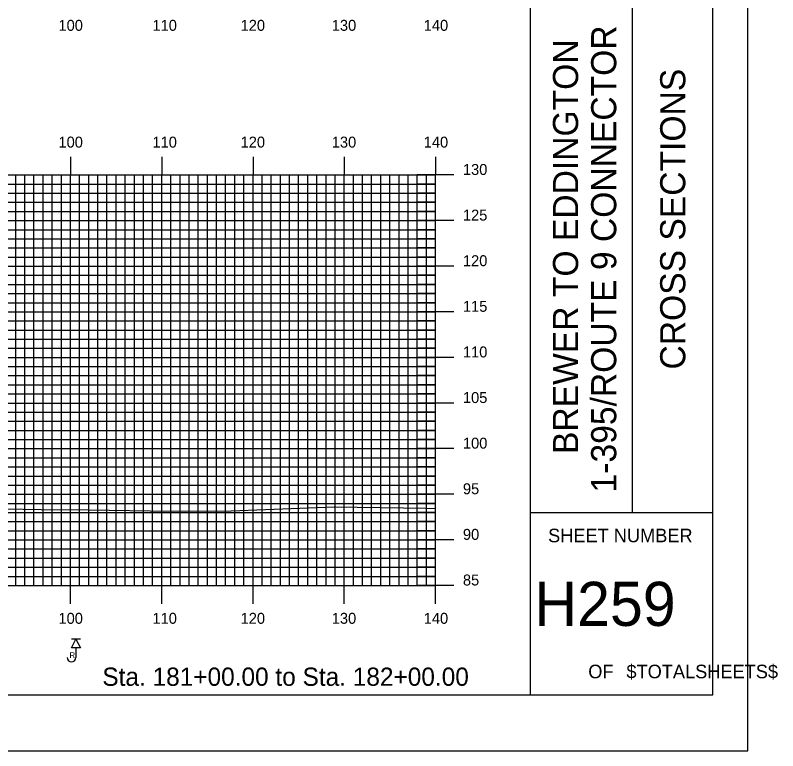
# Model space of a CAD drawing. Extents: x 1786189 to 1786532, y 442591 to 442811.
# Drawn here: x 1786448.5 to 1786532.1, y 442590.5 to 442671.2 of the extents above; entities that cross this region are included whole.
import ezdxf

# ---------------------------------------------------------------- set-up
doc = ezdxf.new("R2010")
doc.units = 0
for name, color, linetype in [('BORDER', 7, 'Continuous'), ('BORING - REFUSAL', 7, 'Continuous'), ('H_V ANNOTATION', 7, 'Continuous'), ('MAJOR', 7, 'Continuous'), ('MINOR', 7, 'Continuous'), ('PLOT BOUNDARY', 7, 'Continuous'), ('S_Roadway_Centerline', 7, 'Continuous')]:
    doc.layers.add(name, color=color, linetype=linetype)

msp = doc.modelspace()

# ---------------------------------------------------------------- linework, layer by layer
at = {"layer": 'BORDER'}
for p, q in [((1786504.965, 442596.665), (1786504.965, 442806.665)), ((1786516.147, 442616.671), (1786516.147, 442686.671)), ((1786504.965, 442616.671), (1786524.965, 442616.671))]:
    msp.add_line(p, q, dxfattribs=at)
msp.add_lwpolyline([(1786204.965, 442596.665), (1786524.965, 442596.665), (1786524.965, 442806.665), (1786204.965, 442806.665)], close=True, dxfattribs=at)
at = {"layer": 'BORING - REFUSAL'}
for p, q in [((1786455.645, 442602.782), (1786454.685, 442602.782)), ((1786455.165, 442601.822), (1786455.165, 442600.763))]:
    msp.add_line(p, q, dxfattribs=at)
msp.add_lwpolyline([(1786455.165, 442602.782), (1786455.645, 442601.822), (1786454.685, 442601.822)], close=True, dxfattribs=at)
msp.add_arc((1786454.68, 442600.763), 0.485, 180, 0, dxfattribs=at)
at = {"layer": 'MAJOR'}
for p, q in [((1786454.565, 442655.669), (1786454.565, 442653.665)), ((1786464.565, 442655.669), (1786464.565, 442653.665)), ((1786474.565, 442655.669), (1786474.565, 442653.665)), ((1786484.565, 442655.669), (1786484.565, 442653.665)), ((1786494.565, 442655.669), (1786494.565, 442653.665)), ((1786214.565, 442653.665), (1786494.565, 442653.665)), ((1786214.565, 442653.665), (1786494.565, 442653.665)), ((1786454.565, 442608.665), (1786454.565, 442653.665)), ((1786464.565, 442608.665), (1786464.565, 442653.665)), ((1786474.565, 442608.665), (1786474.565, 442653.665)), ((1786484.565, 442608.665), (1786484.565, 442653.665)), ((1786496.569, 442653.665), (1786492.561, 442653.665)), ((1786494.565, 442608.665), (1786494.565, 442653.665)), ((1786494.565, 442608.665), (1786494.565, 442653.665)), ((1786214.565, 442648.665), (1786494.565, 442648.665)), ((1786496.569, 442648.665), (1786492.561, 442648.665)), ((1786214.565, 442643.665), (1786494.565, 442643.665)), ((1786496.569, 442643.665), (1786492.561, 442643.665)), ((1786214.565, 442638.665), (1786494.565, 442638.665)), ((1786496.569, 442638.665), (1786492.561, 442638.665)), ((1786214.565, 442633.665), (1786494.565, 442633.665)), ((1786496.569, 442633.665), (1786492.561, 442633.665)), ((1786214.565, 442628.665), (1786494.565, 442628.665)), ((1786496.569, 442628.665), (1786492.561, 442628.665)), ((1786214.565, 442623.665), (1786494.565, 442623.665)), ((1786496.569, 442623.665), (1786492.561, 442623.665)), ((1786214.565, 442618.665), (1786494.565, 442618.665)), ((1786496.569, 442618.665), (1786492.561, 442618.665)), ((1786214.565, 442613.665), (1786494.565, 442613.665)), ((1786496.569, 442613.665), (1786492.561, 442613.665)), ((1786214.565, 442608.665), (1786494.565, 442608.665)), ((1786214.565, 442608.665), (1786494.565, 442608.665)), ((1786454.565, 442606.661), (1786454.565, 442608.665)), ((1786464.565, 442606.661), (1786464.565, 442608.665)), ((1786474.565, 442606.661), (1786474.565, 442608.665)), ((1786484.565, 442606.661), (1786484.565, 442608.665)), ((1786496.569, 442608.665), (1786492.561, 442608.665)), ((1786494.565, 442606.661), (1786494.565, 442608.665))]:
    msp.add_line(p, q, dxfattribs=at)
at = {"layer": 'MINOR'}
for p, q in [((1786448.565, 442608.665), (1786448.565, 442653.665)), ((1786449.565, 442608.665), (1786449.565, 442653.665)), ((1786450.565, 442608.665), (1786450.565, 442653.665)), ((1786451.565, 442608.665), (1786451.565, 442653.665)), ((1786452.565, 442608.665), (1786452.565, 442653.665)), ((1786453.565, 442608.665), (1786453.565, 442653.665)), ((1786455.565, 442608.665), (1786455.565, 442653.665)), ((1786456.565, 442608.665), (1786456.565, 442653.665)), ((1786457.565, 442608.665), (1786457.565, 442653.665)), ((1786458.565, 442608.665), (1786458.565, 442653.665)), ((1786459.565, 442608.665), (1786459.565, 442653.665)), ((1786460.565, 442608.665), (1786460.565, 442653.665)), ((1786461.565, 442608.665), (1786461.565, 442653.665)), ((1786462.565, 442608.665), (1786462.565, 442653.665)), ((1786463.565, 442608.665), (1786463.565, 442653.665)), ((1786465.565, 442608.665), (1786465.565, 442653.665)), ((1786466.565, 442608.665), (1786466.565, 442653.665)), ((1786467.565, 442608.665), (1786467.565, 442653.665)), ((1786468.565, 442608.665), (1786468.565, 442653.665)), ((1786469.565, 442608.665), (1786469.565, 442653.665)), ((1786470.565, 442608.665), (1786470.565, 442653.665)), ((1786471.565, 442608.665), (1786471.565, 442653.665)), ((1786472.565, 442608.665), (1786472.565, 442653.665)), ((1786473.565, 442608.665), (1786473.565, 442653.665)), ((1786475.565, 442608.665), (1786475.565, 442653.665)), ((1786476.565, 442608.665), (1786476.565, 442653.665)), ((1786477.565, 442608.665), (1786477.565, 442653.665)), ((1786478.565, 442608.665), (1786478.565, 442653.665)), ((1786479.565, 442608.665), (1786479.565, 442653.665)), ((1786480.565, 442608.665), (1786480.565, 442653.665)), ((1786481.565, 442608.665), (1786481.565, 442653.665)), ((1786482.565, 442608.665), (1786482.565, 442653.665)), ((1786483.565, 442608.665), (1786483.565, 442653.665)), ((1786485.565, 442608.665), (1786485.565, 442653.665)), ((1786486.565, 442608.665), (1786486.565, 442653.665)), ((1786487.565, 442608.665), (1786487.565, 442653.665)), ((1786488.565, 442608.665), (1786488.565, 442653.665)), ((1786489.565, 442608.665), (1786489.565, 442653.665)), ((1786490.565, 442608.665), (1786490.565, 442653.665)), ((1786491.565, 442608.665), (1786491.565, 442653.665)), ((1786492.565, 442608.665), (1786492.565, 442653.665)), ((1786493.565, 442608.665), (1786493.565, 442653.665)), ((1786214.565, 442652.665), (1786494.565, 442652.665)), ((1786494.565, 442652.665), (1786492.561, 442652.665)), ((1786214.565, 442651.665), (1786494.565, 442651.665)), ((1786494.565, 442651.665), (1786492.561, 442651.665)), ((1786214.565, 442650.665), (1786494.565, 442650.665)), ((1786494.565, 442650.665), (1786492.561, 442650.665)), ((1786214.565, 442649.665), (1786494.565, 442649.665)), ((1786494.565, 442649.665), (1786492.561, 442649.665)), ((1786214.565, 442647.665), (1786494.565, 442647.665)), ((1786494.565, 442647.665), (1786492.561, 442647.665)), ((1786214.565, 442646.665), (1786494.565, 442646.665)), ((1786494.565, 442646.665), (1786492.561, 442646.665)), ((1786214.565, 442645.665), (1786494.565, 442645.665)), ((1786494.565, 442645.665), (1786492.561, 442645.665)), ((1786214.565, 442644.665), (1786494.565, 442644.665)), ((1786494.565, 442644.665), (1786492.561, 442644.665)), ((1786214.565, 442642.665), (1786494.565, 442642.665)), ((1786494.565, 442642.665), (1786492.561, 442642.665)), ((1786214.565, 442641.665), (1786494.565, 442641.665)), ((1786494.565, 442641.665), (1786492.561, 442641.665)), ((1786214.565, 442640.665), (1786494.565, 442640.665)), ((1786494.565, 442640.665), (1786492.561, 442640.665)), ((1786214.565, 442639.665), (1786494.565, 442639.665)), ((1786494.565, 442639.665), (1786492.561, 442639.665)), ((1786214.565, 442637.665), (1786494.565, 442637.665)), ((1786494.565, 442637.665), (1786492.561, 442637.665)), ((1786214.565, 442636.665), (1786494.565, 442636.665)), ((1786494.565, 442636.665), (1786492.561, 442636.665)), ((1786214.565, 442635.665), (1786494.565, 442635.665)), ((1786494.565, 442635.665), (1786492.561, 442635.665)), ((1786214.565, 442634.665), (1786494.565, 442634.665)), ((1786494.565, 442634.665), (1786492.561, 442634.665)), ((1786214.565, 442632.665), (1786494.565, 442632.665)), ((1786494.565, 442632.665), (1786492.561, 442632.665)), ((1786214.565, 442631.665), (1786494.565, 442631.665)), ((1786494.565, 442631.665), (1786492.561, 442631.665)), ((1786214.565, 442630.665), (1786494.565, 442630.665)), ((1786494.565, 442630.665), (1786492.561, 442630.665)), ((1786214.565, 442629.665), (1786494.565, 442629.665)), ((1786494.565, 442629.665), (1786492.561, 442629.665)), ((1786214.565, 442627.665), (1786494.565, 442627.665)), ((1786494.565, 442627.665), (1786492.561, 442627.665)), ((1786214.565, 442626.665), (1786494.565, 442626.665)), ((1786494.565, 442626.665), (1786492.561, 442626.665)), ((1786214.565, 442625.665), (1786494.565, 442625.665)), ((1786494.565, 442625.665), (1786492.561, 442625.665)), ((1786214.565, 442624.665), (1786494.565, 442624.665)), ((1786494.565, 442624.665), (1786492.561, 442624.665)), ((1786214.565, 442622.665), (1786494.565, 442622.665)), ((1786494.565, 442622.665), (1786492.561, 442622.665)), ((1786214.565, 442621.665), (1786494.565, 442621.665)), ((1786494.565, 442621.665), (1786492.561, 442621.665)), ((1786214.565, 442620.665), (1786494.565, 442620.665)), ((1786494.565, 442620.665), (1786492.561, 442620.665)), ((1786214.565, 442619.665), (1786494.565, 442619.665)), ((1786494.565, 442619.665), (1786492.561, 442619.665)), ((1786214.565, 442617.665), (1786494.565, 442617.665)), ((1786494.565, 442617.665), (1786492.561, 442617.665)), ((1786214.565, 442616.665), (1786494.565, 442616.665)), ((1786494.565, 442616.665), (1786492.561, 442616.665)), ((1786214.565, 442615.665), (1786494.565, 442615.665)), ((1786494.565, 442615.665), (1786492.561, 442615.665)), ((1786214.565, 442614.665), (1786494.565, 442614.665)), ((1786494.565, 442614.665), (1786492.561, 442614.665)), ((1786214.565, 442612.665), (1786494.565, 442612.665)), ((1786494.565, 442612.665), (1786492.561, 442612.665)), ((1786214.565, 442611.665), (1786494.565, 442611.665)), ((1786494.565, 442611.665), (1786492.561, 442611.665)), ((1786214.565, 442610.665), (1786494.565, 442610.665)), ((1786494.565, 442610.665), (1786492.561, 442610.665)), ((1786214.565, 442609.665), (1786494.565, 442609.665)), ((1786494.565, 442609.665), (1786492.561, 442609.665))]:
    msp.add_line(p, q, dxfattribs=at)
at = {"layer": 'PLOT BOUNDARY'}
msp.add_lwpolyline([(1786188.778, 442590.547), (1786528.778, 442590.547), (1786528.778, 442810.547), (1786188.778, 442810.547)], close=True, dxfattribs=at)
at = {"layer": 'S_Roadway_Centerline'}
msp.add_lwpolyline([(1786437.485, 442617.231), (1786451.358, 442617.004), (1786456.562, 442616.964), (1786465.509, 442616.823), (1786472.168, 442616.839), (1786483.452, 442617.268), (1786493.562, 442617.121), (1786494.565, 442617.11)], dxfattribs=at)

# ---------------------------------------------------------------- texts
at = {"layer": 'BORDER'}
for s, p in [('1-395/ROUTE 9 CONNECTOR', (1786514.368, 442618.865)), ('BREWER TO EDDINGTON', (1786510.188, 442623.074)), ('CROSS SECTIONS', (1786521.934, 442632.339))]:
    msp.add_text(s, height=2.75575, rotation=90, dxfattribs=at).set_placement(p)
for s, height, p in [('SHEET NUMBER', 1.49054, (1786506.896, 442613.398)), ('H259', 4.8388, (1786505.404, 442604.23)), ('OF', 1.4905, (1786511.299, 442598.491)), ('$TOTALSHEETS$', 1.49054, (1786515.478, 442598.491))]:
    msp.add_text(s, height=height, dxfattribs=at).set_placement(p)
at = {"layer": 'BORING - REFUSAL'}
msp.add_text('R', height=0.64, dxfattribs=at).set_placement((1786454.456, 442600.708))
at = {"layer": 'H_V ANNOTATION'}
for s, height, p in [('100', 1.2, (1786453.248, 442669.465)), ('110', 1.2, (1786463.548, 442669.465)), ('120', 1.2, (1786473.205, 442669.465)), ('130', 1.2, (1786483.195, 442669.465)), ('140', 1.2, (1786493.27, 442669.465)), ('100', 1.2, (1786453.248, 442656.665)), ('110', 1.2, (1786463.548, 442656.665)), ('120', 1.2, (1786473.205, 442656.665)), ('130', 1.2, (1786483.195, 442656.665)), ('140', 1.2, (1786493.27, 442656.665)), ('130', 1.2, (1786497.565, 442653.665)), ('125', 1.2, (1786497.565, 442648.665)), ('120', 1.2, (1786497.565, 442643.665)), ('115', 1.2, (1786497.565, 442638.665)), ('110', 1.2, (1786497.565, 442633.665)), ('105', 1.2, (1786497.565, 442628.665)), ('100', 1.2, (1786497.565, 442623.665)), ('95', 1.2, (1786497.565, 442618.665)), ('90', 1.2, (1786497.565, 442613.665)), ('85', 1.2, (1786497.565, 442608.665)), ('100', 1.2, (1786453.248, 442604.465)), ('110', 1.2, (1786463.548, 442604.465)), ('120', 1.2, (1786473.205, 442604.465)), ('130', 1.2, (1786483.195, 442604.465)), ('140', 1.2, (1786493.27, 442604.465)), ('Sta. 181+00.00 to Sta. 182+00.00', 2.0004, (1786458.056, 442597.665))]:
    msp.add_text(s, height=height, dxfattribs=at).set_placement(p)

doc.saveas('drawing.dxf')
